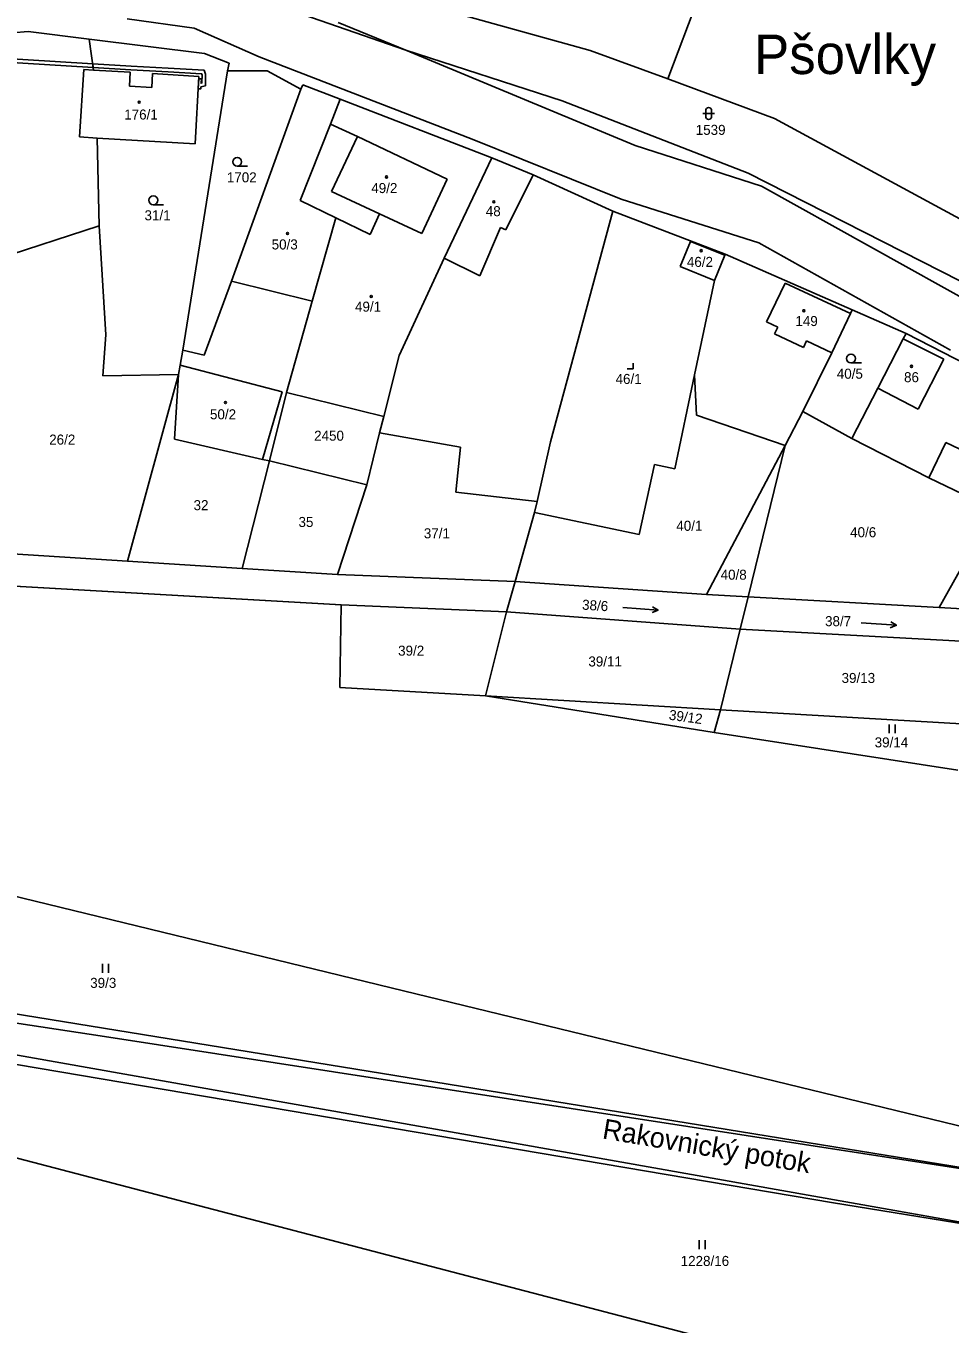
# Model space of a CAD drawing. Extents: x -801826 to -800592, y -1032871 to -1031813.
# Drawn here: x -801281.1 to -801124.4, y -1032516 to -1032295.9 of the extents above; entities that cross this region are included whole.
import ezdxf

# ---------------------------------------------------------------- set-up
doc = ezdxf.new("R2010")
doc.units = 0
for name, color, linetype in [('Vrstva 1', 7, 'Continuous'), ('Vrstva 15', 7, 'Continuous'), ('Vrstva 18', 7, 'Continuous'), ('Vrstva 19', 7, 'Continuous'), ('Vrstva 25', 7, 'Continuous'), ('Vrstva 27', 7, 'Continuous'), ('Vrstva 4', 7, 'Continuous')]:
    doc.layers.add(name, color=color, linetype=linetype)

msp = doc.modelspace()

# ---------------------------------------------------------------- linework, layer by layer
at = {"layer": 'Vrstva 1'}
for p, q in [((-801162.68, -1032279.42), (-801172.28, -1032304.86)), ((-801253.19, -1032287.31), (-801216.74, -1032299.98)), ((-801185.47, -1032300.06), (-801215.82, -1032291.6)), ((-801263.98, -1032294.66), (-801252.6, -1032296.27)), ((-801216.74, -1032299.98), (-801228.18, -1032295.28)), ((-801306.97, -1032299.09), (-801280.76, -1032296.82)), ((-801280.76, -1032296.82), (-801270.43, -1032298.1)), ((-801252.6, -1032296.27), (-801241.6, -1032301.11)), ((-801270.43, -1032298.1), (-801250.88, -1032300.53)), ((-801269.66, -1032303.37), (-801270.43, -1032298.1)), ((-801190.22, -1032308.58), (-801216.74, -1032299.98)), ((-801177.86, -1032316.17), (-801216.74, -1032299.98)), ((-801172.28, -1032304.86), (-801185.47, -1032300.06)), ((-801250.88, -1032300.53), (-801246.68, -1032302.2)), ((-801246.68, -1032302.2), (-801246.95, -1032303.5)), ((-801241.6, -1032301.11), (-801205.48, -1032315.09)), ((-801272.03, -1032314.71), (-801271.29, -1032303.25)), ((-801271.29, -1032303.25), (-801269.66, -1032303.37)), ((-801269.66, -1032303.37), (-801263.47, -1032303.74)), ((-801263.47, -1032303.74), (-801263.6, -1032306.09)), ((-801259.78, -1032306.3), (-801259.65, -1032303.95)), ((-801259.65, -1032303.95), (-801251.8, -1032304.45)), ((-801254.56, -1032350.83), (-801246.95, -1032303.5)), ((-801251.8, -1032304.45), (-801252.46, -1032315.86)), ((-801240.24, -1032303.47), (-801246.95, -1032303.5)), ((-801234.53, -1032306.63), (-801240.24, -1032303.47)), ((-801263.6, -1032306.09), (-801259.78, -1032306.3)), ((-801246.29, -1032339.15), (-801234.53, -1032306.63)), ((-801234.21, -1032305.86), (-801234.53, -1032306.63)), ((-801227.87, -1032308.29), (-801234.21, -1032305.86)), ((-801154.2, -1032311.57), (-801172.28, -1032304.86)), ((-801229.47, -1032312.55), (-801227.87, -1032308.29)), ((-801202.13, -1032318.27), (-801227.87, -1032308.29)), ((-801158.69, -1032320.84), (-801190.22, -1032308.58)), ((-801229.47, -1032312.55), (-801234.65, -1032325.5)), ((-801224.93, -1032314.62), (-801229.47, -1032312.55)), ((-801107.26, -1032337.02), (-801154.2, -1032311.57)), ((-801269.05, -1032314.89), (-801272.03, -1032314.71)), ((-801252.46, -1032315.86), (-801269.05, -1032314.89)), ((-801268.74, -1032329.75), (-801269.05, -1032314.89)), ((-801209.74, -1032321.87), (-801224.93, -1032314.62)), ((-801205.48, -1032315.09), (-801180.22, -1032325.28)), ((-801156.42, -1032323.04), (-801177.86, -1032316.17)), ((-801210.2, -1032335.27), (-801202.13, -1032318.27)), ((-801202.13, -1032318.27), (-801195.15, -1032321.1)), ((-801213.99, -1032331.08), (-801209.74, -1032321.87)), ((-801181.63, -1032327.3), (-801195.15, -1032321.1)), ((-801090.72, -1032355.44), (-801158.69, -1032320.84)), ((-801100.28, -1032354.34), (-801156.42, -1032323.04)), ((-801234.65, -1032325.5), (-801228.6, -1032328.42)), ((-801180.22, -1032325.28), (-801156.86, -1032332.67)), ((-801232.59, -1032342.55), (-801228.6, -1032328.42)), ((-801228.6, -1032328.42), (-801222.78, -1032331.22)), ((-801222.78, -1032331.22), (-801221.16, -1032327.74)), ((-801221.16, -1032327.74), (-801213.99, -1032331.08)), ((-801181.63, -1032327.3), (-801192.22, -1032366.39)), ((-801162.56, -1032334.57), (-801181.63, -1032327.3)), ((-801287.15, -1032335.8), (-801268.74, -1032329.75)), ((-801268.74, -1032329.75), (-801287.15, -1032335.8)), ((-801268.74, -1032329.75), (-801267.56, -1032348.23)), ((-801267.56, -1032348.23), (-801268.74, -1032329.75)), ((-801168.43, -1032332.41), (-801170.2, -1032336.68)), ((-801162.65, -1032334.77), (-801168.43, -1032332.41)), ((-801156.86, -1032332.67), (-801124.35, -1032350.83)), ((-801217.88, -1032351.75), (-801210.2, -1032335.27)), ((-801164.4, -1032339.04), (-801162.65, -1032334.77)), ((-801162.56, -1032334.57), (-801162.65, -1032334.77)), ((-801141.03, -1032344.01), (-801162.56, -1032334.57)), ((-801170.2, -1032336.68), (-801164.4, -1032339.04)), ((-801246.29, -1032339.15), (-801250.94, -1032351.7)), ((-801246.29, -1032339.15), (-801232.59, -1032342.55)), ((-801167.78, -1032355.03), (-801164.4, -1032339.04)), ((-801236.95, -1032358.03), (-801232.59, -1032342.55)), ((-801141.35, -1032344.66), (-801141.03, -1032344.01)), ((-801131.91, -1032348.04), (-801141.03, -1032344.01)), ((-801144.52, -1032351.31), (-801141.35, -1032344.66)), ((-801267.56, -1032348.23), (-801268.09, -1032355.19)), ((-801268.09, -1032355.19), (-801267.56, -1032348.23)), ((-801132.4, -1032348.96), (-801131.91, -1032348.04)), ((-801131.91, -1032348.04), (-801107.8, -1032360.39)), ((-801136.69, -1032357.32), (-801132.4, -1032348.96)), ((-801254.97, -1032353.38), (-801254.56, -1032350.83)), ((-801250.94, -1032351.7), (-801254.56, -1032350.83)), ((-801220.48, -1032362.09), (-801217.88, -1032351.75)), ((-801144.52, -1032351.31), (-801149.43, -1032361.26)), ((-801268.09, -1032355.19), (-801255.29, -1032355.01)), ((-801255.29, -1032355.01), (-801268.09, -1032355.19)), ((-801255.29, -1032355.01), (-801263.9, -1032386.64)), ((-801263.9, -1032386.64), (-801255.29, -1032355.01)), ((-801255.29, -1032355.01), (-801263.9, -1032386.64)), ((-801255.95, -1032365.97), (-801255.29, -1032355.01)), ((-801255.95, -1032365.97), (-801255.29, -1032355.01)), ((-801255.29, -1032355.01), (-801254.97, -1032353.38)), ((-801171.1, -1032371), (-801167.78, -1032355.03)), ((-801167.78, -1032355.03), (-801167.46, -1032361.9)), ((-801141.08, -1032365.86), (-801136.69, -1032357.32)), ((-801239.81, -1032369.64), (-801236.95, -1032358.03)), ((-801236.95, -1032358.03), (-801220.48, -1032362.09)), ((-801152.41, -1032367.01), (-801149.43, -1032361.26)), ((-801141.08, -1032365.86), (-801149.43, -1032361.26)), ((-801220.48, -1032362.09), (-801221.16, -1032364.85)), ((-801167.46, -1032361.9), (-801152.41, -1032367.01)), ((-801241.01, -1032369.39), (-801255.95, -1032365.97)), ((-801241.01, -1032369.39), (-801255.95, -1032365.97)), ((-801221.16, -1032364.85), (-801223.35, -1032373.7)), ((-801221.16, -1032364.85), (-801207.45, -1032367.3)), ((-801128.07, -1032372.48), (-801141.08, -1032365.86)), ((-801207.45, -1032367.3), (-801208.27, -1032374.92)), ((-801192.22, -1032366.39), (-801194.48, -1032376.52)), ((-801152.41, -1032367.01), (-801165.72, -1032392.29)), ((-801152.41, -1032367.01), (-801158.66, -1032392.7)), ((-801239.81, -1032369.64), (-801244.45, -1032387.86)), ((-801244.45, -1032387.86), (-801239.81, -1032369.64)), ((-801239.81, -1032369.64), (-801244.45, -1032387.86)), ((-801239.81, -1032369.64), (-801241.01, -1032369.39)), ((-801239.81, -1032369.64), (-801241.01, -1032369.39)), ((-801223.35, -1032373.7), (-801239.81, -1032369.64)), ((-801223.35, -1032373.7), (-801239.81, -1032369.64)), ((-801177.16, -1032382.11), (-801174.57, -1032370.24)), ((-801174.57, -1032370.24), (-801171.1, -1032371)), ((-801117.49, -1032377.59), (-801128.07, -1032372.48)), ((-801228.32, -1032388.88), (-801223.35, -1032373.7)), ((-801228.32, -1032388.88), (-801223.35, -1032373.7)), ((-801208.27, -1032374.92), (-801194.48, -1032376.52)), ((-801194.48, -1032376.52), (-801194.89, -1032378.36)), ((-801198.17, -1032390.11), (-801194.89, -1032378.36)), ((-801194.89, -1032378.36), (-801177.16, -1032382.11)), ((-801116.96, -1032377.78), (-801126.31, -1032394.49)), ((-801293.31, -1032384.79), (-801263.9, -1032386.64)), ((-801293.31, -1032384.79), (-801263.9, -1032386.64)), ((-801263.9, -1032386.64), (-801293.31, -1032384.79)), ((-801227.68, -1032394.03), (-801339.88, -1032387.67)), ((-801339.88, -1032387.67), (-801227.68, -1032394.03)), ((-801227.68, -1032394.03), (-801339.88, -1032387.67)), ((-801263.9, -1032386.64), (-801244.45, -1032387.86)), ((-801263.9, -1032386.64), (-801244.45, -1032387.86)), ((-801244.45, -1032387.86), (-801263.9, -1032386.64)), ((-801244.45, -1032387.86), (-801228.32, -1032388.88)), ((-801244.45, -1032387.86), (-801228.32, -1032388.88)), ((-801228.32, -1032388.88), (-801244.45, -1032387.86)), ((-801198.17, -1032390.11), (-801228.32, -1032388.88)), ((-801198.17, -1032390.11), (-801228.32, -1032388.88)), ((-801199.67, -1032395.22), (-801198.17, -1032390.11)), ((-801199.67, -1032395.22), (-801198.17, -1032390.11)), ((-801165.72, -1032392.29), (-801198.17, -1032390.11)), ((-801158.66, -1032392.7), (-801165.72, -1032392.29)), ((-801227.91, -1032408.04), (-801227.68, -1032394.03)), ((-801227.91, -1032408.04), (-801227.68, -1032394.03)), ((-801227.68, -1032394.03), (-801227.91, -1032408.04)), ((-801199.67, -1032395.22), (-801227.68, -1032394.03)), ((-801227.68, -1032394.03), (-801199.67, -1032395.22)), ((-801199.67, -1032395.22), (-801227.68, -1032394.03)), ((-801158.66, -1032392.7), (-801160.03, -1032398.16)), ((-801126.31, -1032394.49), (-801158.66, -1032392.7)), ((-801117.46, -1032394.97), (-801126.31, -1032394.49)), ((-801203.19, -1032409.48), (-801199.67, -1032395.22)), ((-801203.19, -1032409.48), (-801199.67, -1032395.22)), ((-801160.03, -1032398.16), (-801199.67, -1032395.22)), ((-801160.03, -1032398.16), (-801163.36, -1032411.83)), ((-801118.61, -1032400.4), (-801160.03, -1032398.16)), ((-801203.19, -1032409.48), (-801227.91, -1032408.04)), ((-801203.19, -1032409.48), (-801227.91, -1032408.04)), ((-801227.91, -1032408.04), (-801203.19, -1032409.48)), ((-801163.36, -1032411.83), (-801203.19, -1032409.48)), ((-801203.19, -1032409.48), (-801164.43, -1032415.66)), ((-801164.43, -1032415.66), (-801203.19, -1032409.48)), ((-801163.36, -1032411.83), (-801164.43, -1032415.66)), ((-801121.52, -1032414.28), (-801163.36, -1032411.83)), ((-801164.43, -1032415.66), (-801123.15, -1032422.09)), ((-801123.15, -1032422.09), (-801164.43, -1032415.66)), ((-801217.1, -1032459.5), (-801342.09, -1032429.1)), ((-801342.09, -1032429.1), (-801217.1, -1032459.5)), ((-801386.46, -1032449.23), (-801268.54, -1032467.11)), ((-801342.15, -1032453.77), (-801097.8, -1032493.48)), ((-801104.67, -1032486.84), (-801217.1, -1032459.5)), ((-801217.1, -1032459.5), (-801104.67, -1032486.84)), ((-801097.8, -1032493.48), (-801268.54, -1032467.11)), ((-801105.37, -1032501.75), (-801290.52, -1032469)), ((-801144.19, -1032495.42), (-801291.7, -1032470.46)), ((-801287.22, -1032486.69), (-801056.37, -1032546.95)), ((-801105.37, -1032501.75), (-801144.19, -1032495.42))]:
    msp.add_line(p, q, dxfattribs=at)
at = {"layer": 'Vrstva 25'}
for p, q in [((-801166.38, -1032310.72), (-801164.38, -1032310.72)), ((-801165.88, -1032311.22), (-801165.88, -1032310.22)), ((-801164.88, -1032311.22), (-801164.88, -1032310.22)), ((-801243.56, -1032319.68), (-801245.31, -1032319.68)), ((-801257.79, -1032326.19), (-801259.54, -1032326.19)), ((-801179.17, -1032354.04), (-801178.17, -1032354.04)), ((-801178.17, -1032354.04), (-801178.17, -1032353.04)), ((-801139.49, -1032353.03), (-801141.24, -1032353.03)), ((-801179.93, -1032394.51), (-801173.95, -1032394.93)), ((-801139.53, -1032397.07), (-801133.55, -1032397.49)), ((-801134.78, -1032414.31), (-801134.78, -1032415.81)), ((-801133.76, -1032415.81), (-801133.76, -1032414.31)), ((-801268.16, -1032454.93), (-801268.16, -1032456.43)), ((-801267.14, -1032456.43), (-801267.14, -1032454.93)), ((-801166.98, -1032501.79), (-801166.98, -1032503.29)), ((-801165.96, -1032503.29), (-801165.96, -1032501.79))]:
    msp.add_line(p, q, dxfattribs=at)
for points in [[(-801174.91, -1032394.36), (-801173.95, -1032394.93), (-801174.98, -1032395.36)], [(-801134.51, -1032396.92), (-801133.55, -1032397.49), (-801134.58, -1032397.92)]]:
    msp.add_lwpolyline(points, dxfattribs=at)
for centre, radius in [((-801261.93, -1032308.8), 0.175), ((-801245.31, -1032318.93), 0.75), ((-801219.99, -1032321.49), 0.175), ((-801259.54, -1032325.44), 0.75), ((-801201.8, -1032325.71), 0.175), ((-801236.77, -1032331.07), 0.175), ((-801166.63, -1032333.99), 0.175), ((-801222.58, -1032341.75), 0.175), ((-801149.25, -1032344.17), 0.175), ((-801141.24, -1032352.28), 0.75), ((-801130.98, -1032353.6), 0.175), ((-801247.31, -1032359.74), 0.175)]:
    msp.add_circle(centre, radius, dxfattribs=at)
for centre, start, end in [((-801165.38, -1032310.22), 0, 180), ((-801165.38, -1032311.22), 180, 0)]:
    msp.add_arc(centre, 0.5, start, end, dxfattribs=at)
at = {"layer": 'Vrstva 27'}
for points in [[(-801307.45, -1032299.73), (-801305.46, -1032300.11), (-801269.81, -1032302.33), (-801269.72, -1032302.93), (-801305.54, -1032300.71), (-801307.59, -1032300.31), (-801310.37, -1032299.55), (-801308.86, -1032299.35), (-801307.45, -1032299.73)], [(-801269.81, -1032302.33), (-801263.32, -1032302.73), (-801257, -1032303.04), (-801250.92, -1032303.4), (-801250.67, -1032304.08), (-801250.69, -1032306.01), (-801251.48, -1032306.23), (-801251.5, -1032306.56), (-801251.92, -1032306.53), (-801251.82, -1032304.83), (-801251.39, -1032304.86), (-801251.44, -1032305.59), (-801251.29, -1032305.55), (-801251.27, -1032304.18), (-801251.34, -1032303.98), (-801257.04, -1032303.64), (-801263.36, -1032303.33), (-801269.72, -1032302.93), (-801269.81, -1032302.33)]]:
    msp.add_lwpolyline(points, dxfattribs=at)
at = {"layer": 'Vrstva 4'}
for p, q in [((-801229.34, -1032323.95), (-801224.93, -1032314.62)), ((-801195.15, -1032321.1), (-801199.78, -1032330.45)), ((-801221.16, -1032327.74), (-801229.34, -1032323.95)), ((-801200.66, -1032330.03), (-801204.16, -1032338.25)), ((-801199.78, -1032330.45), (-801200.66, -1032330.03)), ((-801210.2, -1032335.27), (-801204.16, -1032338.25)), ((-801152.41, -1032339.48), (-801155.58, -1032346.06)), ((-801141.35, -1032344.66), (-801152.41, -1032339.48)), ((-801155.58, -1032346.06), (-801153.65, -1032346.97)), ((-801153.65, -1032346.97), (-801154.19, -1032348.09)), ((-801154.19, -1032348.09), (-801149.31, -1032350.41)), ((-801149.31, -1032350.41), (-801148.77, -1032349.29)), ((-801148.77, -1032349.29), (-801144.52, -1032351.31)), ((-801125.52, -1032352.41), (-801132.4, -1032348.96)), ((-801129.85, -1032360.84), (-801125.52, -1032352.41)), ((-801254.97, -1032353.38), (-801237.7, -1032357.92)), ((-801136.69, -1032357.32), (-801129.85, -1032360.84)), ((-801237.7, -1032357.92), (-801241.01, -1032369.39)), ((-801128.07, -1032372.48), (-801125.18, -1032366.49)), ((-801125.18, -1032366.49), (-801114.49, -1032371.64))]:
    msp.add_line(p, q, dxfattribs=at)

# ---------------------------------------------------------------- texts
at = {"layer": 'Vrstva 15'}
msp.add_text('Pšovlky', height=6.7, dxfattribs=at).set_placement((-801157.69, -1032304.04))
msp.add_text('Rakovnický potok', height=3.4, rotation=350.4304, dxfattribs=at).set_placement((-801183.54, -1032484.5))
at = {"layer": 'Vrstva 18'}
for s, p in [('1539', (-801167.57, -1032314.35)), ('1702', (-801247.07, -1032322.4)), ('31/1', (-801261.03, -1032328.84)), ('40/5', (-801143.65, -1032355.7)), ('26/2', (-801277.19, -1032366.87)), ('2450', (-801232.27, -1032366.21)), ('32', (-801252.71, -1032377.99)), ('35', (-801234.92, -1032380.84)), ('37/1', (-801213.67, -1032382.76)), ('40/1', (-801170.86, -1032381.49)), ('40/6', (-801141.39, -1032382.58)), ('40/8', (-801163.35, -1032389.78)), ('38/7', (-801145.64, -1032397.66)), ('39/2', (-801218.03, -1032402.66)), ('39/11', (-801185.77, -1032404.49)), ('39/13', (-801142.84, -1032407.29)), ('39/14', (-801137.23, -1032418.21)), ('39/3', (-801270.24, -1032458.99)), ('1228/16', (-801170.12, -1032506.14))]:
    msp.add_text(s, height=1.7, dxfattribs=at).set_placement(p)
for s, rotation, p in [('38/6', 356.1867, (-801186.88, -1032394.84)), ('39/12', 352.2316, (-801172.19, -1032413.5))]:
    msp.add_text(s, height=1.7, rotation=rotation, dxfattribs=at).set_placement(p)
at = {"layer": 'Vrstva 19'}
for s, p in [('176/1', (-801264.47, -1032311.75)), ('49/2', (-801222.58, -1032324.22)), ('48', (-801203.16, -1032328.14)), ('50/3', (-801239.47, -1032333.78)), ('46/2', (-801169.07, -1032336.74)), ('49/1', (-801225.34, -1032344.33)), ('149', (-801150.67, -1032346.77)), ('46/1', (-801181.16, -1032356.59)), ('86', (-801132.25, -1032356.29)), ('50/2', (-801249.93, -1032362.58))]:
    msp.add_text(s, height=1.7, dxfattribs=at).set_placement(p)

doc.saveas('drawing.dxf')
